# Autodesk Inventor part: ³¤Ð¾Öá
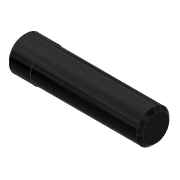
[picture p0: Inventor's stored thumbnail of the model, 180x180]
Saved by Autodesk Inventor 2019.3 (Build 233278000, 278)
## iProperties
Created: 2017-10
Part Number: ³¤Ð¾Öá
Material: Ogólny
Document SubType Name: Modeling
Designer: CADENGINEERING4
Density: 1 g/cm^3
Appearance: Gładki — czarny
Author: CADENGINEERING4
Revision Number: ÈÎºÎ
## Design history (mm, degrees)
feature "Ðý×ª1"
node "Bryła1"
